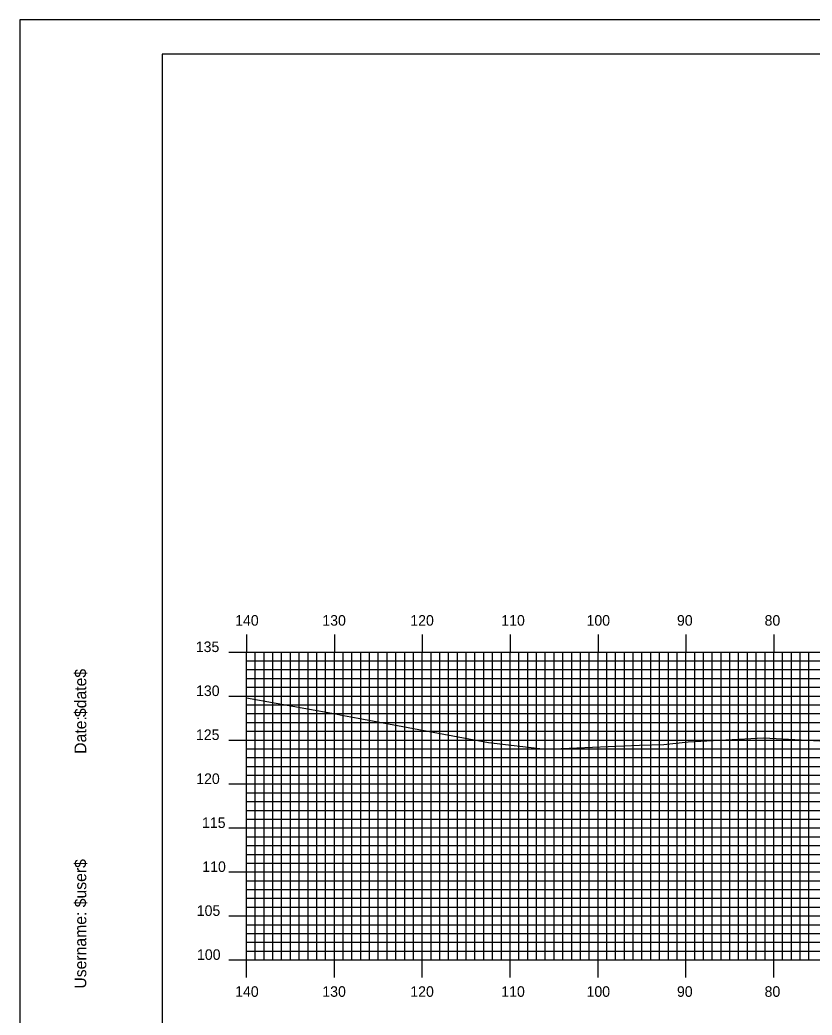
# Model space of a CAD drawing. Extents: x 1766907 to 1767250, y 442591 to 442811.
# Drawn here: x 1766906.6 to 1766996.8, y 442697.4 to 442810.5 of the extents above; entities that cross this region are included whole.
import ezdxf

# ---------------------------------------------------------------- set-up
doc = ezdxf.new("R2010")
doc.units = 0
for name, color, linetype in [('BORDER', 7, 'Continuous'), ('H_V ANNOTATION', 7, 'Continuous'), ('MAJOR', 7, 'Continuous'), ('MINOR', 7, 'Continuous'), ('PLOT BOUNDARY', 7, 'Continuous'), ('S_Roadway_Centerline', 7, 'Continuous')]:
    doc.layers.add(name, color=color, linetype=linetype)

msp = doc.modelspace()

# ---------------------------------------------------------------- linework, layer by layer
at = {"layer": 'BORDER'}
msp.add_lwpolyline([(1766922.82, 442596.67), (1767242.82, 442596.67), (1767242.82, 442806.67), (1766922.82, 442806.67)], close=True, dxfattribs=at)
at = {"layer": 'MAJOR'}
for p, q in [((1766932.42, 442740.67), (1766932.42, 442738.67)), ((1766942.42, 442740.67), (1766942.42, 442738.67)), ((1766952.42, 442740.67), (1766952.42, 442738.67)), ((1766962.42, 442740.67), (1766962.42, 442738.67)), ((1766972.42, 442740.67), (1766972.42, 442738.67)), ((1766982.42, 442740.67), (1766982.42, 442738.67)), ((1766992.42, 442740.67), (1766992.42, 442738.67)), ((1766930.42, 442738.67), (1766932.42, 442738.67)), ((1766932.42, 442738.67), (1767212.42, 442738.67)), ((1766932.42, 442703.67), (1766932.42, 442738.67)), ((1766932.42, 442703.67), (1766932.42, 442738.67)), ((1766932.42, 442738.67), (1767212.42, 442738.67)), ((1766942.42, 442703.67), (1766942.42, 442738.67)), ((1766952.42, 442703.67), (1766952.42, 442738.67)), ((1766962.42, 442703.67), (1766962.42, 442738.67)), ((1766972.42, 442703.67), (1766972.42, 442738.67)), ((1766982.42, 442703.67), (1766982.42, 442738.67)), ((1766992.42, 442703.67), (1766992.42, 442738.67)), ((1766930.42, 442733.67), (1766932.42, 442733.67)), ((1766932.42, 442733.67), (1767212.42, 442733.67)), ((1766930.42, 442728.67), (1766932.42, 442728.67)), ((1766932.42, 442728.67), (1767212.42, 442728.67)), ((1766930.42, 442723.67), (1766932.42, 442723.67)), ((1766932.42, 442723.67), (1767212.42, 442723.67)), ((1766930.42, 442718.67), (1766932.42, 442718.67)), ((1766932.42, 442718.67), (1767212.42, 442718.67)), ((1766930.42, 442713.67), (1766932.42, 442713.67)), ((1766932.42, 442713.67), (1767212.42, 442713.67)), ((1766930.42, 442708.67), (1766932.42, 442708.67)), ((1766932.42, 442708.67), (1767212.42, 442708.67)), ((1766930.42, 442703.67), (1766932.42, 442703.67)), ((1766932.42, 442703.67), (1767212.42, 442703.67)), ((1766932.42, 442703.67), (1767212.42, 442703.67)), ((1766932.42, 442701.66), (1766932.42, 442703.67)), ((1766942.42, 442701.66), (1766942.42, 442703.67)), ((1766952.42, 442701.66), (1766952.42, 442703.67)), ((1766962.42, 442701.66), (1766962.42, 442703.67)), ((1766972.42, 442701.66), (1766972.42, 442703.67)), ((1766982.42, 442701.66), (1766982.42, 442703.67)), ((1766992.42, 442701.66), (1766992.42, 442703.67))]:
    msp.add_line(p, q, dxfattribs=at)
at = {"layer": 'MINOR'}
for p, q in [((1766932.42, 442737.67), (1767212.42, 442737.67)), ((1766932.42, 442737.67), (1766934.43, 442737.67)), ((1766933.42, 442703.67), (1766933.42, 442738.67)), ((1766934.42, 442703.67), (1766934.42, 442738.67)), ((1766935.42, 442703.67), (1766935.42, 442738.67)), ((1766936.42, 442703.67), (1766936.42, 442738.67)), ((1766937.42, 442703.67), (1766937.42, 442738.67)), ((1766938.42, 442703.67), (1766938.42, 442738.67)), ((1766939.42, 442703.67), (1766939.42, 442738.67)), ((1766940.42, 442703.67), (1766940.42, 442738.67)), ((1766941.42, 442703.67), (1766941.42, 442738.67)), ((1766943.42, 442703.67), (1766943.42, 442738.67)), ((1766944.42, 442703.67), (1766944.42, 442738.67)), ((1766945.42, 442703.67), (1766945.42, 442738.67)), ((1766946.42, 442703.67), (1766946.42, 442738.67)), ((1766947.42, 442703.67), (1766947.42, 442738.67)), ((1766948.42, 442703.67), (1766948.42, 442738.67)), ((1766949.42, 442703.67), (1766949.42, 442738.67)), ((1766950.42, 442703.67), (1766950.42, 442738.67)), ((1766951.42, 442703.67), (1766951.42, 442738.67)), ((1766953.42, 442703.67), (1766953.42, 442738.67)), ((1766954.42, 442703.67), (1766954.42, 442738.67)), ((1766955.42, 442703.67), (1766955.42, 442738.67)), ((1766956.42, 442703.67), (1766956.42, 442738.67)), ((1766957.42, 442703.67), (1766957.42, 442738.67)), ((1766958.42, 442703.67), (1766958.42, 442738.67)), ((1766959.42, 442703.67), (1766959.42, 442738.67)), ((1766960.42, 442703.67), (1766960.42, 442738.67)), ((1766961.42, 442703.67), (1766961.42, 442738.67)), ((1766963.42, 442703.67), (1766963.42, 442738.67)), ((1766964.42, 442703.67), (1766964.42, 442738.67)), ((1766965.42, 442703.67), (1766965.42, 442738.67)), ((1766966.42, 442703.67), (1766966.42, 442738.67)), ((1766967.42, 442703.67), (1766967.42, 442738.67)), ((1766968.42, 442703.67), (1766968.42, 442738.67)), ((1766969.42, 442703.67), (1766969.42, 442738.67)), ((1766970.42, 442703.67), (1766970.42, 442738.67)), ((1766971.42, 442703.67), (1766971.42, 442738.67)), ((1766973.42, 442703.67), (1766973.42, 442738.67)), ((1766974.42, 442703.67), (1766974.42, 442738.67)), ((1766975.42, 442703.67), (1766975.42, 442738.67)), ((1766976.42, 442703.67), (1766976.42, 442738.67)), ((1766977.42, 442703.67), (1766977.42, 442738.67)), ((1766978.42, 442703.67), (1766978.42, 442738.67)), ((1766979.42, 442703.67), (1766979.42, 442738.67)), ((1766980.42, 442703.67), (1766980.42, 442738.67)), ((1766981.42, 442703.67), (1766981.42, 442738.67)), ((1766983.42, 442703.67), (1766983.42, 442738.67)), ((1766984.42, 442703.67), (1766984.42, 442738.67)), ((1766985.42, 442703.67), (1766985.42, 442738.67)), ((1766986.42, 442703.67), (1766986.42, 442738.67)), ((1766987.42, 442703.67), (1766987.42, 442738.67)), ((1766988.42, 442703.67), (1766988.42, 442738.67)), ((1766989.42, 442703.67), (1766989.42, 442738.67)), ((1766990.42, 442703.67), (1766990.42, 442738.67)), ((1766991.42, 442703.67), (1766991.42, 442738.67)), ((1766993.42, 442703.67), (1766993.42, 442738.67)), ((1766994.42, 442703.67), (1766994.42, 442738.67)), ((1766995.42, 442703.67), (1766995.42, 442738.67)), ((1766996.42, 442703.67), (1766996.42, 442738.67)), ((1766932.42, 442736.67), (1767212.42, 442736.67)), ((1766932.42, 442736.67), (1766934.43, 442736.67)), ((1766932.42, 442735.67), (1767212.42, 442735.67)), ((1766932.42, 442735.67), (1766934.43, 442735.67)), ((1766932.42, 442734.67), (1767212.42, 442734.67)), ((1766932.42, 442734.67), (1766934.43, 442734.67)), ((1766932.42, 442732.67), (1767212.42, 442732.67)), ((1766932.42, 442732.67), (1766934.43, 442732.67)), ((1766932.42, 442731.67), (1767212.42, 442731.67)), ((1766932.42, 442731.67), (1766934.43, 442731.67)), ((1766932.42, 442730.67), (1767212.42, 442730.67)), ((1766932.42, 442730.67), (1766934.43, 442730.67)), ((1766932.42, 442729.67), (1767212.42, 442729.67)), ((1766932.42, 442729.67), (1766934.43, 442729.67)), ((1766932.42, 442727.67), (1767212.42, 442727.67)), ((1766932.42, 442727.67), (1766934.43, 442727.67)), ((1766932.42, 442726.67), (1767212.42, 442726.67)), ((1766932.42, 442726.67), (1766934.43, 442726.67)), ((1766932.42, 442725.67), (1767212.42, 442725.67)), ((1766932.42, 442725.67), (1766934.43, 442725.67)), ((1766932.42, 442724.67), (1767212.42, 442724.67)), ((1766932.42, 442724.67), (1766934.43, 442724.67)), ((1766932.42, 442722.67), (1767212.42, 442722.67)), ((1766932.42, 442722.67), (1766934.43, 442722.67)), ((1766932.42, 442721.67), (1767212.42, 442721.67)), ((1766932.42, 442721.67), (1766934.43, 442721.67)), ((1766932.42, 442720.67), (1767212.42, 442720.67)), ((1766932.42, 442720.67), (1766934.43, 442720.67)), ((1766932.42, 442719.67), (1767212.42, 442719.67)), ((1766932.42, 442719.67), (1766934.43, 442719.67)), ((1766932.42, 442717.67), (1767212.42, 442717.67)), ((1766932.42, 442717.67), (1766934.43, 442717.67)), ((1766932.42, 442716.67), (1767212.42, 442716.67)), ((1766932.42, 442716.67), (1766934.43, 442716.67)), ((1766932.42, 442715.67), (1767212.42, 442715.67)), ((1766932.42, 442715.67), (1766934.43, 442715.67)), ((1766932.42, 442714.67), (1767212.42, 442714.67)), ((1766932.42, 442714.67), (1766934.43, 442714.67)), ((1766932.42, 442712.67), (1767212.42, 442712.67)), ((1766932.42, 442712.67), (1766934.43, 442712.67)), ((1766932.42, 442711.67), (1767212.42, 442711.67)), ((1766932.42, 442711.67), (1766934.43, 442711.67)), ((1766932.42, 442710.67), (1767212.42, 442710.67)), ((1766932.42, 442710.67), (1766934.43, 442710.67)), ((1766932.42, 442709.67), (1767212.42, 442709.67)), ((1766932.42, 442709.67), (1766934.43, 442709.67)), ((1766932.42, 442707.67), (1767212.42, 442707.67)), ((1766932.42, 442707.67), (1766934.43, 442707.67)), ((1766932.42, 442706.67), (1767212.42, 442706.67)), ((1766932.42, 442706.67), (1766934.43, 442706.67)), ((1766932.42, 442705.67), (1767212.42, 442705.67)), ((1766932.42, 442705.67), (1766934.43, 442705.67)), ((1766932.42, 442704.67), (1767212.42, 442704.67)), ((1766932.42, 442704.67), (1766934.43, 442704.67))]:
    msp.add_line(p, q, dxfattribs=at)
at = {"layer": 'PLOT BOUNDARY'}
msp.add_lwpolyline([(1766906.64, 442590.55), (1767246.64, 442590.55), (1767246.64, 442810.55), (1766906.64, 442810.55)], close=True, dxfattribs=at)
at = {"layer": 'S_Roadway_Centerline'}
msp.add_lwpolyline([(1766932.42, 442733.48), (1766942.53, 442731.64), (1766943.44, 442731.46), (1766945.12, 442731.15), (1766959.96, 442728.38), (1766966.45, 442727.61), (1766977.14, 442728.07), (1766979.89, 442728.15), (1766982.66, 442728.45), (1766991.24, 442728.92), (1767000.5, 442728.41)], dxfattribs=at)

# ---------------------------------------------------------------- texts
at = {"layer": 'BORDER'}
for s, p in [('$date$', (1766914.19, 442731.28)), ('Date:', (1766914.19, 442727.1)), ('$user$', (1766914.19, 442709.65)), ('Username:', (1766914.19, 442700.4))]:
    msp.add_text(s, height=1.339, rotation=90, dxfattribs=at).set_placement(p)
at = {"layer": 'H_V ANNOTATION'}
for s, p in [('140', (1766931.13, 442741.67)), ('130', (1766941.05, 442741.67)), ('120', (1766951.06, 442741.67)), ('110', (1766961.41, 442741.67)), ('100', (1766971.11, 442741.67)), ('90', (1766981.4, 442741.67)), ('80', (1766991.37, 442741.67)), ('135', (1766926.65, 442738.67)), ('130', (1766926.68, 442733.67)), ('125', (1766926.67, 442728.67)), ('120', (1766926.7, 442723.67)), ('115', (1766927.36, 442718.67)), ('110', (1766927.39, 442713.67)), ('105', (1766926.76, 442708.67)), ('100', (1766926.79, 442703.67)), ('140', (1766931.13, 442699.47)), ('130', (1766941.05, 442699.47)), ('120', (1766951.06, 442699.47)), ('110', (1766961.41, 442699.47)), ('100', (1766971.11, 442699.47)), ('90', (1766981.4, 442699.47)), ('80', (1766991.37, 442699.47))]:
    msp.add_text(s, height=1.2, dxfattribs=at).set_placement(p)
at = {"layer": 'MAJOR'}
msp.add_text('-', height=0.012, dxfattribs=at).set_placement((1766932.41, 442703.67))

doc.saveas('drawing.dxf')
